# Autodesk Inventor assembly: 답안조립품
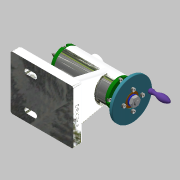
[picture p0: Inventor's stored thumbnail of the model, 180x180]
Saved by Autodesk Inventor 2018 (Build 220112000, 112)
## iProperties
Created: 2022-06
Part Number: 답안조립품
Material: 일반
Document SubType Name: Assembly
Designer: home
Author: home
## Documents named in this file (18)
- C:\Users\home\Desktop\720606V1019\답안조립품.iam
- C:\Users\home\Desktop\720606V1019\본체.ipt
- C:\Users\home\Desktop\720606V1019\커버.ipt
- C:\Users\home\Desktop\720606V1019\부시.ipt
- C:\Users\home\Desktop\720606V1019\나사축.ipt
- C:\Users\home\Desktop\720606V1019\키 4 x 4 x 10.ipt
- C:\Users\home\Desktop\720606V1019\플랜지.ipt
- C:\Users\home\Desktop\720606V1019\돌림판.ipt
- C:\Users\home\Desktop\720606V1019\볼트 M3.ipt
- C:\Users\home\Desktop\720606V1019\핸들.ipt
- C:\Users\home\Desktop\720606V1019\와셔.ipt
- C:\Users\home\Desktop\720606V1019\너트 M8.ipt
- C:\Users\home\Desktop\720606V1019\슬리브.ipt
- C:\Users\home\Desktop\720606V1019\센터홀더.ipt
- C:\Users\home\Desktop\720606V1019\센터.ipt
- C:\Users\home\Desktop\720606V1019\나사.ipt
- C:\Users\home\Desktop\720606V1019\멈춤나사 M3.ipt
- C:\Users\home\Desktop\720606V1019\중공축.ipt
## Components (2 placed, 2 different names)
1. 플랜지:1
2. 핸들:1
